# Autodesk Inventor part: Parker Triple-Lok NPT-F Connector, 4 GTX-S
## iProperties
Shininess: 20.0
Length Units: 11272
Angle Units: 11279
Time Units: 11290
Mass Units: 11286
Length Display Precision: 3
Angle Display Precision: 2
Created: 2001-09
Part Number: Parker Triple-Lok NPT-F Connector, 4 GTX-S
Material: Stainless Steel, Austenitic
Description: Parker Triple-Lok NPT-F Connector, 4 GTX-S
Document SubType Name: Modeling
Designer: jhagarty
Density: 0.0
Volumn: 0.0
Area: 0.0
PropertySet Name: Model Information
Control State: 0
Master: False
Checked Out: False
Last Check In By: Charles Bliss
Last Check In Date: 2003-09-27
Author: jhagarty
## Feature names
1. Extrusion1
2. Revolution3
3. Mirror2
4. Revolution1
5. Hole3
6. Extrusion4
